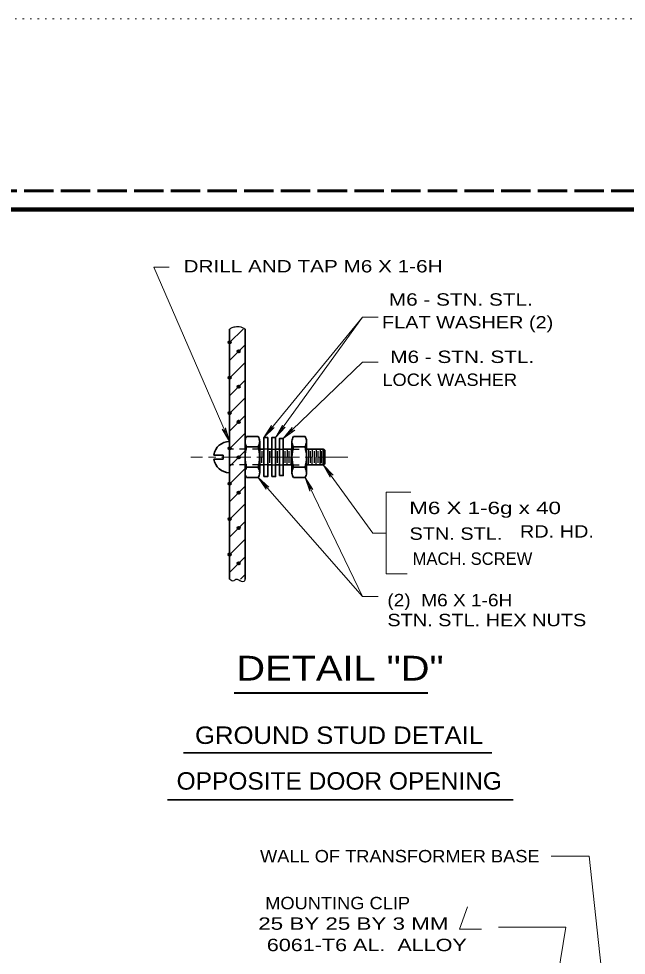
# Model space of a CAD drawing. Extents: x 312583 to 312854, y 144419 to 144597.
# Drawn here: x 312757.4 to 312794.6, y 144539.3 to 144596.8 of the extents above; entities that cross this region are included whole.
import ezdxf

# ---------------------------------------------------------------- set-up
doc = ezdxf.new("R2010")
doc.units = 0
doc.header["$LTSCALE"] = 0.3
doc.header["$PDMODE"] = 32
doc.header["$PDSIZE"] = 0.15
for name, pattern in [('DOTTED', [1.5, 0.3, -1.2]), ('LONG_DASH_SHORT_DASH', [9.9, 6, -1.2, 1.5, -1.2]), ('LONG_DASHED', [7.5, 6, -1.5]), ('SHORT_DASHED', [2.7, 1.5, -1.2])]:
    doc.linetypes.add(name, pattern=pattern)
for name, color, linetype, lineweight in [('1', 7, 'Continuous', 40), ('2', 7, 'Continuous', 13), ('62', 7, 'DOTTED', 13), ('63', 7, 'LONG_DASHED', 60)]:
    doc.layers.add(name, color=color, linetype=linetype, lineweight=lineweight)

msp = doc.modelspace()

# ---------------------------------------------------------------- linework, layer by layer
at = {"layer": '1', "lineweight": 35}
for p, q in [((312770.2971, 144562.4121), (312770.2971, 144577.7455)), ((312771.2554, 144562.4121), (312771.2554, 144577.7455)), ((312771.2478, 144570.8838), (312771.2478, 144569.9025)), ((312771.3398, 144571.1598), (312772.0604, 144571.1598)), ((312772.1448, 144570.8838), (312772.1448, 144569.9025)), ((312774.1228, 144570.8838), (312774.1228, 144569.9025)), ((312774.2148, 144571.1598), (312774.9354, 144571.1598)), ((312775.0198, 144570.8838), (312775.0198, 144569.9025)), ((312769.3388, 144570.0251), (312769.8984, 144570.0251)), ((312769.8984, 144570.0251), (312769.8984, 144569.7798)), ((312771.3398, 144570.5311), (312772.0604, 144570.5311)), ((312772.1601, 144570.3778), (312772.4054, 144570.3778)), ((312772.6431, 144570.3778), (312772.8808, 144570.3778)), ((312773.1184, 144570.3778), (312773.3561, 144570.3778)), ((312773.5938, 144570.3778), (312774.1228, 144570.3778)), ((312774.2148, 144570.5311), (312774.9354, 144570.5311)), ((312775.0198, 144570.3778), (312776.0471, 144570.3778)), ((312776.0471, 144570.3778), (312776.0471, 144569.9025)), ((312769.3388, 144569.7798), (312769.8984, 144569.7798)), ((312771.2478, 144568.9211), (312771.2478, 144569.9025)), ((312772.1448, 144568.9211), (312772.1448, 144569.9025)), ((312774.1228, 144568.9211), (312774.1228, 144569.9025)), ((312775.0198, 144568.9211), (312775.0198, 144569.9025)), ((312776.0471, 144569.4195), (312776.0471, 144569.9025)), ((312771.3398, 144569.2738), (312772.0604, 144569.2738)), ((312772.1601, 144569.4195), (312772.4054, 144569.4195)), ((312772.6431, 144569.4195), (312772.8808, 144569.4195)), ((312773.1184, 144569.4195), (312773.3561, 144569.4195)), ((312773.5938, 144569.4195), (312774.1228, 144569.4195)), ((312774.2148, 144569.2738), (312774.9354, 144569.2738)), ((312775.0198, 144569.4195), (312776.0471, 144569.4195)), ((312771.3398, 144568.6451), (312772.0604, 144568.6451)), ((312774.2148, 144568.6451), (312774.9354, 144568.6451))]:
    msp.add_line(p, q, dxfattribs=at)
at = {"layer": '1', "lineweight": 13}
for p, q in [((312770.2971, 144576.9175), (312771.1328, 144577.7455)), ((312770.2971, 144575.8288), (312771.2554, 144576.7871)), ((312770.2971, 144574.7478), (312771.2554, 144575.7061)), ((312770.2971, 144573.6591), (312771.2554, 144574.6175)), ((312770.2894, 144572.5781), (312771.2554, 144573.5365)), ((312770.2971, 144571.4895), (312771.2554, 144572.4555)), ((312770.2971, 144570.4085), (312771.2554, 144571.3668)), ((312770.2971, 144569.3275), (312771.2554, 144570.2858)), ((312770.2971, 144568.2388), (312771.2554, 144569.1971)), ((312770.2971, 144567.1578), (312771.2554, 144568.1161)), ((312770.2971, 144566.0691), (312771.2554, 144567.0351)), ((312770.2971, 144564.9881), (312771.2554, 144565.9465)), ((312770.2971, 144563.9071), (312771.2554, 144564.8655)), ((312770.2971, 144562.8185), (312771.2554, 144563.7768)), ((312770.9718, 144562.4121), (312771.2554, 144562.6958))]:
    msp.add_line(p, q, dxfattribs=at)
at = {"layer": '1', "linetype": 'SHORT_DASHED', "lineweight": 25}
for p, q in [((312772.1601, 144570.3778), (312770.2971, 144570.3778)), ((312772.6431, 144570.3778), (312772.4054, 144570.3778)), ((312772.8808, 144570.3778), (312773.1184, 144570.3778)), ((312773.3561, 144570.3778), (312773.5938, 144570.3778)), ((312774.1228, 144570.3778), (312775.0198, 144570.3778)), ((312772.1601, 144569.4195), (312770.2971, 144569.4195)), ((312772.6431, 144569.4195), (312772.4054, 144569.4195)), ((312772.8808, 144569.4195), (312773.1184, 144569.4195)), ((312773.3561, 144569.4195), (312773.5938, 144569.4195)), ((312774.1228, 144569.4195), (312775.0198, 144569.4195))]:
    msp.add_line(p, q, dxfattribs=at)
at = {"layer": '1', "lineweight": 25}
for p, q in [((312772.2828, 144570.2628), (312772.2828, 144569.9025)), ((312772.7581, 144570.2628), (312772.7581, 144569.9025)), ((312772.7581, 144569.5421), (312772.7581, 144570.2628)), ((312773.2411, 144569.5421), (312773.2411, 144570.2628)), ((312773.7164, 144569.5421), (312773.7164, 144570.2628)), ((312773.8314, 144570.3855), (312773.8314, 144569.9025)), ((312773.9541, 144569.5421), (312773.9541, 144570.2628)), ((312774.0691, 144570.3855), (312774.0691, 144569.9025)), ((312775.1348, 144570.3855), (312775.1348, 144569.9025)), ((312775.2651, 144569.5421), (312775.2651, 144570.2628)), ((312775.3724, 144570.3855), (312775.3724, 144569.9025)), ((312775.5028, 144569.5421), (312775.5028, 144570.2628)), ((312775.6101, 144570.3855), (312775.6101, 144569.9025)), ((312775.7251, 144569.5421), (312775.7251, 144570.2628)), ((312775.8478, 144570.3855), (312775.8478, 144569.9025)), ((312775.9398, 144569.5345), (312775.9398, 144570.2551)), ((312772.2828, 144569.5421), (312772.2828, 144569.9025)), ((312772.7581, 144569.5421), (312772.7581, 144569.9025)), ((312773.8314, 144569.4195), (312773.8314, 144569.9025)), ((312774.0691, 144569.4195), (312774.0691, 144569.9025)), ((312775.1348, 144569.4195), (312775.1348, 144569.9025)), ((312775.3724, 144569.4195), (312775.3724, 144569.9025)), ((312775.6101, 144569.4195), (312775.6101, 144569.9025)), ((312775.8478, 144569.4195), (312775.8478, 144569.9025))]:
    msp.add_line(p, q, dxfattribs=at)
at = {"layer": '1', "linetype": 'LONG_DASH_SHORT_DASH', "lineweight": 13}
msp.add_line((312777.5498, 144569.9025), (312767.9204, 144569.9025), dxfattribs=at)
at = {"layer": '1', "lineweight": 158}
msp.add_lwpolyline([(312616.5, 144423.1446), (312616.5, 144585.0846), (312849, 144585.0846)], dxfattribs=at)
at = {"layer": '1', "lineweight": 35}
for points in [[(312772.4054, 144568.7065), (312772.6431, 144568.7065), (312772.6431, 144571.0985), (312772.4054, 144571.0985)], [(312772.8808, 144568.7065), (312773.1184, 144568.7065), (312773.1184, 144571.0985), (312772.8808, 144571.0985)], [(312773.3561, 144568.7678), (312773.5938, 144568.7678), (312773.5938, 144571.0371), (312773.3561, 144571.0371)]]:
    msp.add_lwpolyline(points, close=True, dxfattribs=at)
for points in [[(312776.0471, 144570.3778), (312776.1314, 144570.3165), (312776.1314, 144569.9025)], [(312776.0471, 144569.4195), (312776.1314, 144569.4808), (312776.1314, 144569.9025)]]:
    msp.add_lwpolyline(points, dxfattribs=at)
at = {"layer": '1', "lineweight": 13}
msp.add_lwpolyline([(312784.89, 144542.3126), (312784.3916, 144540.9403), (312785.741, 144540.9403)], dxfattribs=at)
at = {"layer": '1', "lineweight": 35}
for centre, radius, start, end in [((312770.2908, 144569.8986), 0.9583, 89.85149, 172.64599), ((312772.701, 144571.1164), 1.4854, 191.77014, 203.36365), ((312771.7668, 144570.8659), 0.5187, 145.8703, 178.33743), ((312771.6238, 144570.8659), 0.5187, 1.66257, 34.1297), ((312770.6896, 144571.1164), 1.4854, 336.63635, 348.22986), ((312775.576, 144571.1164), 1.4854, 191.77014, 203.36365), ((312774.6418, 144570.8659), 0.5187, 145.8703, 178.33743), ((312774.4988, 144570.8659), 0.5187, 1.66257, 34.1297), ((312773.5646, 144571.1164), 1.4854, 336.63635, 348.22986), ((312773.9267, 144569.8334), 2.6807, 164.99798, 178.595), ((312769.4639, 144569.8334), 2.6807, 1.405, 15.00202), ((312776.8017, 144569.8334), 2.6807, 164.99798, 178.595), ((312772.3389, 144569.8334), 2.6807, 1.405, 15.00202), ((312770.2908, 144569.8986), 0.9583, 187.12299, 270.14851), ((312773.9267, 144569.9648), 2.6807, 181.405, 195.00202), ((312769.4639, 144569.9648), 2.6807, 344.99798, 358.595), ((312776.8017, 144569.9648), 2.6807, 181.405, 195.00202), ((312772.3389, 144569.9648), 2.6807, 344.99798, 358.595), ((312772.701, 144568.6819), 1.4854, 156.63635, 168.22986), ((312771.7668, 144568.9324), 0.5187, 181.66257, 214.1297), ((312770.6896, 144568.6819), 1.4854, 11.77014, 23.36365), ((312771.6238, 144568.9324), 0.5187, 325.8703, 358.33743), ((312775.576, 144568.6819), 1.4854, 156.63635, 168.22986), ((312774.6418, 144568.9324), 0.5187, 181.66257, 214.1297), ((312773.5646, 144568.6819), 1.4854, 11.77014, 23.36365), ((312774.4988, 144568.9324), 0.5187, 325.8703, 358.33743)]:
    msp.add_arc(centre, radius, start, end, dxfattribs=at)
at = {"layer": '1', "lineweight": 25}
for points in [[(312770.2971, 144577.7455), (312770.4504, 144577.8451), (312770.7188, 144577.8988), (312770.8951, 144577.8988), (312771.2554, 144577.7455)], [(312770.2971, 144562.4121), (312770.5731, 144562.3278), (312770.7188, 144562.4198), (312770.9181, 144562.3278), (312771.2401, 144562.3278), (312771.2554, 144562.4121)]]:
    msp.add_spline(points, degree=3, dxfattribs=at)
at = {"layer": '1'}
for p in [(312770.3124, 144576.9328), (312770.8568, 144576.3885), (312770.3124, 144574.7631), (312770.8568, 144574.2188), (312770.3124, 144572.5935), (312770.8568, 144572.0568), (312770.3124, 144570.4315), (312770.8568, 144569.8871), (312770.3124, 144568.2618), (312770.8568, 144567.7175), (312770.3124, 144566.0921), (312770.8568, 144565.5478), (312770.3124, 144563.9225), (312770.8568, 144563.3781)]:
    msp.add_point(p, dxfattribs=at)
at = {"layer": '2'}
for p, q in [((312765.6448, 144581.5518), (312770.2971, 144570.8608)), ((312765.6448, 144581.5518), (312766.6031, 144581.5518)), ((312778.4544, 144578.4815), (312772.4054, 144571.0985)), ((312778.4544, 144578.4815), (312773.1184, 144571.0985)), ((312778.4544, 144578.4815), (312779.4128, 144578.4815)), ((312778.4544, 144575.7138), (312773.5938, 144571.0371)), ((312778.4544, 144575.7138), (312779.4128, 144575.7138)), ((312772.4054, 144571.0985), (312772.8731, 144571.8421)), ((312772.8731, 144571.8421), (312772.7811, 144571.5585)), ((312773.1184, 144571.0985), (312773.5401, 144571.8651)), ((312773.1184, 144571.0985), (312773.7164, 144571.7425)), ((312773.5401, 144571.8651), (312773.4634, 144571.5815)), ((312773.7164, 144571.7425), (312773.4634, 144571.5815)), ((312769.8524, 144571.6121), (312770.0594, 144571.3975)), ((312770.2971, 144570.8608), (312769.8524, 144571.6121)), ((312770.0518, 144571.6965), (312770.0594, 144571.3975)), ((312770.2971, 144570.8608), (312770.0518, 144571.6965)), ((312772.4054, 144571.0985), (312773.0418, 144571.7041)), ((312773.0418, 144571.7041), (312772.7811, 144571.5585)), ((312773.5938, 144571.0371), (312774.1458, 144571.7195)), ((312773.5938, 144571.0371), (312774.2914, 144571.5585)), ((312774.1458, 144571.7195), (312774.0231, 144571.4511)), ((312774.2914, 144571.5585), (312774.0231, 144571.4511)), ((312779.0908, 144565.2335), (312776.0471, 144569.4195)), ((312776.0471, 144569.4195), (312776.4688, 144568.6605)), ((312776.0471, 144569.4195), (312776.6451, 144568.7831)), ((312776.4688, 144568.6605), (312776.3998, 144568.9441)), ((312776.6451, 144568.7831), (312776.3998, 144568.9441)), ((312778.4544, 144561.3465), (312772.0604, 144568.6451)), ((312772.0604, 144568.6451), (312772.5511, 144567.9245)), ((312772.0604, 144568.6451), (312772.7121, 144568.0625)), ((312778.4544, 144561.3465), (312774.9354, 144568.6451)), ((312774.9354, 144568.6451), (312775.2114, 144567.8171)), ((312774.9354, 144568.6451), (312775.4031, 144567.9091)), ((312772.5511, 144567.9245), (312772.4514, 144568.2005)), ((312772.7121, 144568.0625), (312772.4514, 144568.2005)), ((312775.2114, 144567.8171), (312775.1884, 144568.1085)), ((312775.4031, 144567.9091), (312775.1884, 144568.1085)), ((312779.9034, 144565.2335), (312779.0908, 144565.2335)), ((312779.9034, 144562.7418), (312781.1991, 144562.7418)), ((312778.4544, 144561.3465), (312779.4128, 144561.3465)), ((312786.7879, 144541.0582), (312790.9202, 144541.0582)), ((312789.1415, 144530.1102), (312790.9202, 144541.0582))]:
    msp.add_line(p, q, dxfattribs=at)
at = {"layer": '2', "lineweight": 40}
msp.add_line((312770.5726, 144555.4386), (312782.4521, 144555.4386), dxfattribs=at)
at = {"layer": '2', "lineweight": 35}
for p, q in [((312767.4638, 144551.7586), (312786.3921, 144551.7586)), ((312766.4928, 144548.8836), (312787.6852, 144548.8836))]:
    msp.add_line(p, q, dxfattribs=at)
at = {"layer": '2'}
for points in [[(312779.9034, 144562.7418), (312779.9034, 144567.7558), (312781.4214, 144567.7558)], [(312790.0124, 144545.4282), (312792.3539, 144545.4282), (312793.6802, 144533.1385), (312791.2039, 144530.3249)]]:
    msp.add_lwpolyline(points, dxfattribs=at)
at = {"layer": '62'}
msp.add_line((312601.2, 144596.7846), (312853.5, 144596.7846), dxfattribs=at)
at = {"layer": '63'}
msp.add_line((312851.75, 144586.2246), (312583.526, 144586.2246), dxfattribs=at)

# ---------------------------------------------------------------- texts
at = {"layer": '2'}
for s, height, width, p in [('DRILL AND TAP M6 X 1-6H ', 0.76, 1.25, (312767.4761, 144581.2233)), ('M6 - STN. STL.', 0.76, 1.25, (312780.0692, 144579.1839)), (' FLAT WASHER (2)', 0.76, 1.2, (312779.3083, 144577.7849)), ('M6 - STN. STL.', 0.76, 1.25, (312780.1545, 144575.6679)), (' LOCK WASHER', 0.76, 1.1, (312779.3591, 144574.2612)), ('M6 X 1-6g x 40', 0.76, 1.35, (312781.3183, 144566.4016)), ('STN. STL.', 0.76, 1.2, (312781.3332, 144564.8223)), ('RD. HD. ', 0.76, 1.2, (312788.1047, 144564.9603)), ('(2)  M6 X 1-6H', 0.76, 1.15, (312779.9749, 144560.7439)), ('STN. STL. HEX NUTS', 0.76, 1.2, (312779.9749, 144559.5239)), ('DETAIL "D"', 1.52, 1.2, (312770.7166, 144556.1904)), ('GROUND STUD DETAIL', 1.07, 1.1, (312768.1792, 144552.3037)), ('OPPOSITE DOOR OPENING', 1.07, 1.05, (312767.0495, 144549.5006)), ('WALL OF TRANSFORMER BASE', 0.76, 1.1, (312772.1673, 144545.0392)), ('MOUNTING CLIP', 0.76, 1.1, (312772.4851, 144542.1621)), (' 25 BY 25 BY 3 MM', 0.76, 1.35, (312771.6761, 144540.9048)), ('6061-T6 AL.  ALLOY', 0.76, 1.3, (312772.5827, 144539.5938))]:
    msp.add_text(s, height=height, dxfattribs=dict(at, width=width)).set_placement(p)
msp.add_text('MACH. SCREW', height=0.76, dxfattribs=at).set_placement((312781.5245, 144563.2879))

doc.saveas('drawing.dxf')
